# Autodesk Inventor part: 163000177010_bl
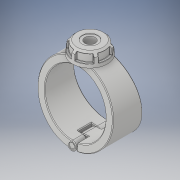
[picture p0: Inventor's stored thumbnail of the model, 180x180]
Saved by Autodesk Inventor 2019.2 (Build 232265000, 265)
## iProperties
Created: 2022-02
Part Number: 163000177010_bl
Material: Generic
Description: Plassadle Threaded 177x1''
Document SubType Name: Modeling
Designer: comp2
Density: 1 g/cm^3
Appearance: Default
Author: comp2
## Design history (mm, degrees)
derived "16300.ipt"
feature "Solid1::16300.ipt" dims "ScaleForDerivedMember" = 10
feature "Solid2::16300.ipt" dims "ScaleForDerivedMember" = 10
feature "Solid3::16300.ipt" dims "ScaleForDerivedMember" = 10
feature "Solid4::16300.ipt" dims "ScaleForDerivedMember" = 10
tag "TaggingFeature1"
body "Solid1"
body "Solid2"
body "Solid3"
body "Solid4"
other parameters: "d0" = 177 [user parameter], "d3" = 88.5 [user parameter], "d7" = 209 [user parameter], "d8" = 85 deg [user parameter], "d9" = 45 deg [user parameter], "d10" = 102 [user parameter], "d11" = 49 [user parameter], "d12" = 25.27 [user parameter], "d13" = 42.84 [user parameter], "d14" = 45.4365 [user parameter], "d42" = 4.3 [user parameter], "d49" = 4.4 [user parameter], "d51" = 0 [user parameter], "d52" = 30.1 [user parameter], "d53" = 121 [user parameter], "d54" = 38.5 [user parameter], "d55" = 0 [user parameter], "d56" = 22 [user parameter], "d57" = 22 [user parameter], "d59" = 0 [user parameter], "d61" = 0 [user parameter], "d62" = 38.5 [user parameter], "d63" = 0 [user parameter], "d65" = 0 [user parameter], "d67" = 0 [user parameter], "d69" = 0 [user parameter], "d70" = 1 [user parameter], "d71" = 105.6 [user parameter], "d72" = 0 [user parameter], "d73" = 2 [user parameter], "d78" = 86.7 [user parameter], "d79" = 5.1 [user parameter], "d80" = 60 deg [user parameter], "d81" = 5.1 [user parameter], "d84" = 0 [user parameter], "d85" = 1 [user parameter], "d87" = 360 deg [user parameter], "d122" = 52 [user parameter], "d124" = 42.80128 [user parameter], "d125" = 1.805 [user parameter], "d127" = 255 [user parameter], "d129" = 30.291 [user parameter], "d130" = 25.74735 [user parameter], "d131" = 33.8 [user parameter], "d132" = 45 deg [user parameter], "d133" = 23.66 [user parameter], "d134" = 15.1455 [user parameter], "d136" = 0 [user parameter], "d138" = 0 [user parameter], "d" = 177 [user parameter], "d1" = 25 [user parameter], "E_" = 54 [user parameter], "E1" = 102 [user parameter], "H1" = 255 [user parameter], "H2" = 52 [user parameter], "H3" = 78 [user parameter], "H_costum" = 49 [user parameter], "Rp" = 30.291 [user parameter], "d128" = 36.1 [user parameter]
